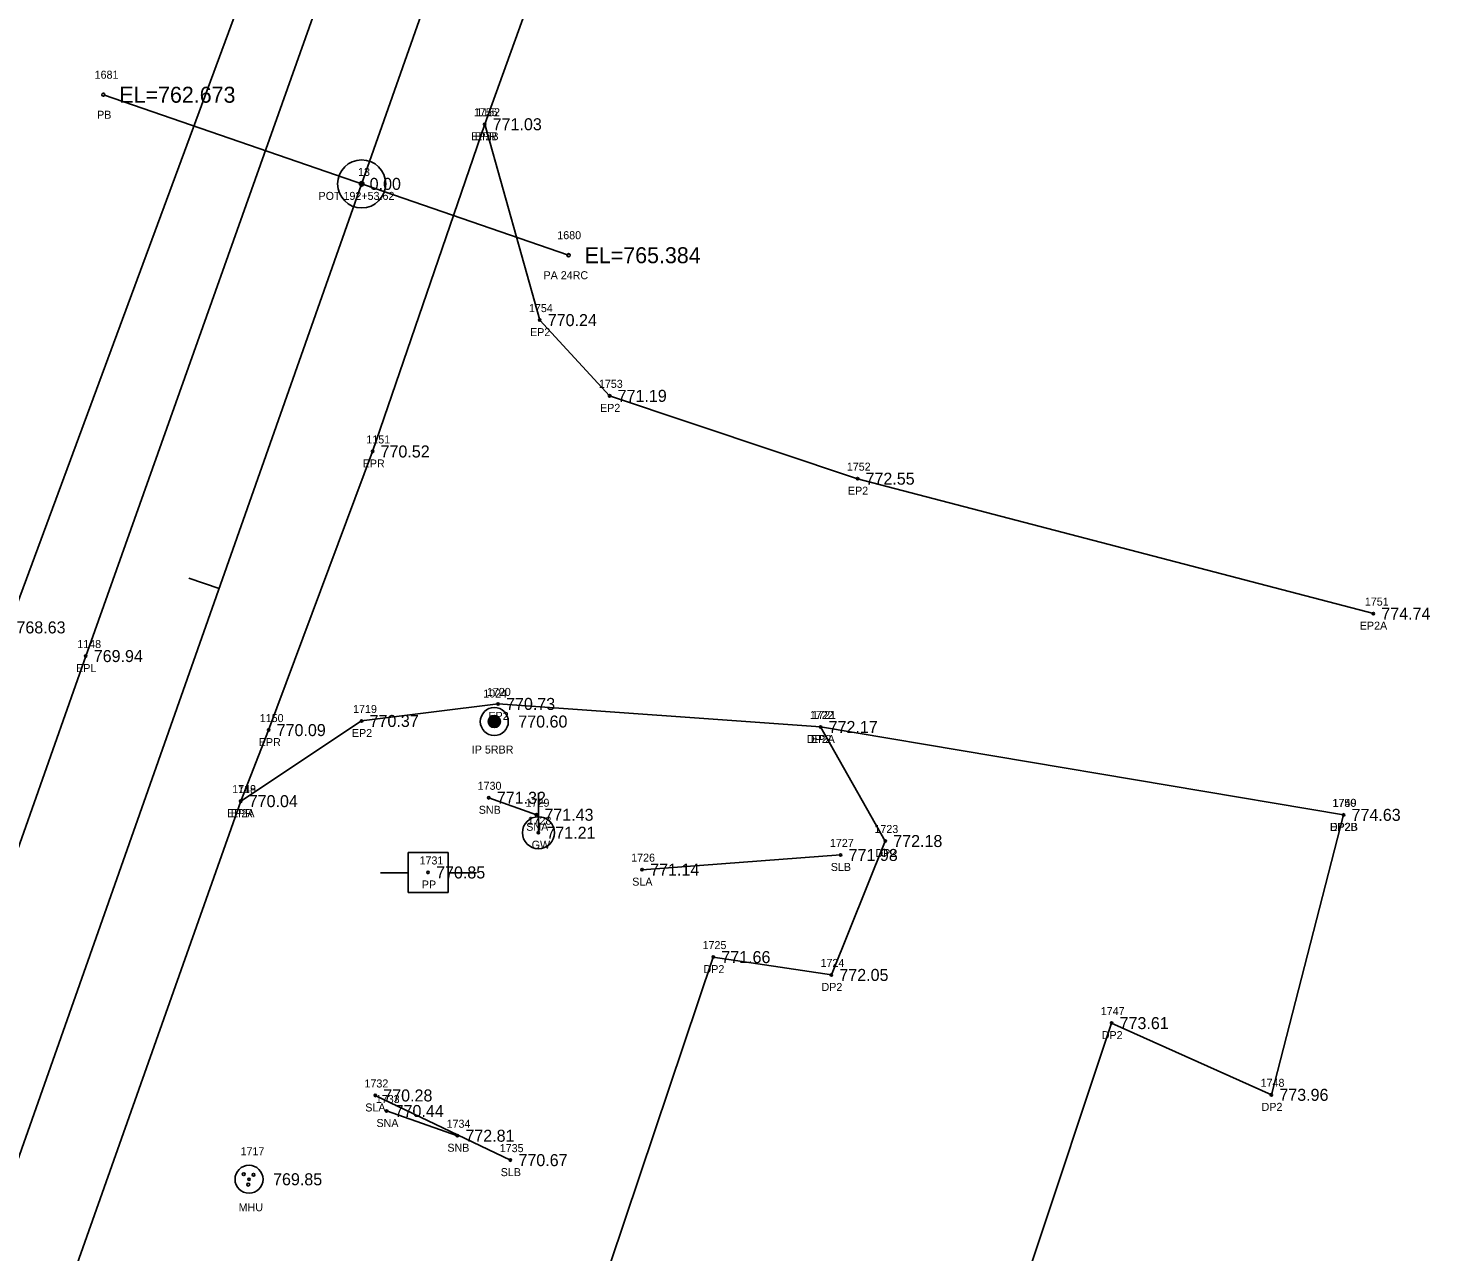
# Model space of a CAD drawing. Extents: x 1736563 to 1738032, y 1150548 to 1154248.
# Drawn here: x 1737815.3 to 1737990.5, y 1153793.3 to 1153946.3 of the extents above; entities that cross this region are included whole.
import ezdxf

# ---------------------------------------------------------------- set-up
doc = ezdxf.new("R2010")
doc.units = 0
for name, color, linetype in [('RD_EX_BldgApp', 7, 'Continuous'), ('RD_EX_BldgApp_txCode', 7, 'Continuous'), ('RD_EX_DR_Inlet', 7, 'Continuous'), ('RD_EX_DR_Pipe', 7, 'Continuous'), ('RD_EX_DR_Pipe_txCode', 7, 'Continuous'), ('RD_EX_Driveway', 7, 'Continuous'), ('RD_EX_Driveway_txCode', 7, 'Continuous'), ('RD_EX_DV_Prop_txCode', 7, 'Continuous'), ('RD_EX_DV_PropPin', 7, 'Continuous'), ('RD_EX_Road', 7, 'Continuous'), ('RD_EX_Road_txCode', 7, 'Continuous'), ('RD_EX_TX_BldgApp_ELEV', 7, 'Continuous'), ('RD_EX_TX_Driveway_ELEV', 7, 'Continuous'), ('RD_EX_TX_DV_Prop_ELEV', 7, 'Continuous'), ('RD_EX_TX_Road_ELEV', 7, 'Continuous'), ('RD_EX_TX_UT_ELEV', 7, 'Continuous'), ('RD_EX_TX_VEG_ELEV', 7, 'Continuous'), ('RD_EX_UT', 7, 'Continuous'), ('RD_EX_UT_txCode', 7, 'Continuous'), ('RD_EX_VEG', 7, 'Continuous'), ('RD_EX_VEG_txCode', 7, 'Continuous'), ('RD_HC_Cl', 7, 'Continuous'), ('RD_HC_Data', 7, 'Continuous'), ('RD_HC_Data_Tic', 7, 'Continuous'), ('RD_HC_Survey_ELEV', 7, 'Continuous'), ('RD_HC_txCode', 7, 'Continuous'), ('RD_SMD_Locator', 7, 'Continuous'), ('RD_TX_Pipe_ElevEX', 7, 'Continuous')]:
    doc.layers.add(name, color=color, linetype=linetype)

msp = doc.modelspace()

# ---------------------------------------------------------------- linework, layer by layer
at = {"layer": 'RD_EX_BldgApp'}
for p, q in [((1737878.86, 1153847.96), (1737872.91, 1153850.08)), ((1737860.15, 1153810.95), (1737868.99, 1153807.86))]:
    msp.add_line(p, q, dxfattribs=at)
at = {"layer": 'RD_EX_DR_Inlet'}
for centre, radius in [((1737842.96, 1153802.42), 1.75), ((1737842.29, 1153803.05), 0.175), ((1737843.52, 1153802.98), 0.175), ((1737842.87, 1153801.75), 0.175)]:
    msp.add_circle(centre, radius, dxfattribs=at)
at = {"layer": 'RD_EX_DR_Pipe'}
msp.add_line((1737882.88, 1153917.87), (1737824.76, 1153937.92), dxfattribs=at)
at = {"layer": 'RD_EX_Driveway'}
msp.add_lwpolyline([(1737914.37, 1153858.93), (1737922.44, 1153844.68), (1737915.71, 1153827.95), (1737900.96, 1153830.18), (1737882.56, 1153775.48), (1737901.6, 1153769.37), (1737890.31, 1153735.49), (1737879.23, 1153704.14), (1737888.54, 1153700.93), (1737902.4, 1153737.89), (1737910.81, 1153737.13), (1737920.2, 1153763.88), (1737930.49, 1153761.11), (1737950.72, 1153821.93), (1737970.68, 1153812.97), (1737979.7, 1153847.95)], dxfattribs=at)
at = {"layer": 'RD_EX_DV_PropPin'}
for p, q in [((1737873.32, 1153858.9), (1737873.32, 1153860.32)), ((1737873.36, 1153858.89), (1737873.36, 1153860.33)), ((1737873.39, 1153858.88), (1737873.39, 1153860.34)), ((1737873.43, 1153858.87), (1737873.43, 1153860.35)), ((1737873.46, 1153858.86), (1737873.46, 1153860.36)), ((1737873.5, 1153858.86), (1737873.5, 1153860.36)), ((1737873.53, 1153858.85), (1737873.53, 1153860.37)), ((1737873.57, 1153858.85), (1737873.57, 1153860.37)), ((1737873.6, 1153858.85), (1737873.6, 1153860.37)), ((1737873.64, 1153858.85), (1737873.64, 1153860.37)), ((1737873.67, 1153858.85), (1737873.67, 1153860.37)), ((1737873.71, 1153858.86), (1737873.71, 1153860.36)), ((1737873.74, 1153858.86), (1737873.74, 1153860.36)), ((1737873.78, 1153858.87), (1737873.78, 1153860.35)), ((1737873.81, 1153858.88), (1737873.81, 1153860.34)), ((1737873.85, 1153858.89), (1737873.85, 1153860.33)), ((1737873.88, 1153858.9), (1737873.88, 1153860.32)), ((1737872.87, 1153859.41), (1737872.87, 1153859.81)), ((1737872.9, 1153859.31), (1737872.9, 1153859.91)), ((1737872.94, 1153859.24), (1737872.94, 1153859.98)), ((1737872.97, 1153859.18), (1737872.97, 1153860.04)), ((1737873.01, 1153859.14), (1737873.01, 1153860.08)), ((1737873.04, 1153859.09), (1737873.04, 1153860.12)), ((1737873.08, 1153859.06), (1737873.08, 1153860.16)), ((1737873.11, 1153859.03), (1737873.11, 1153860.19)), ((1737873.15, 1153859), (1737873.15, 1153860.22)), ((1737873.18, 1153858.98), (1737873.18, 1153860.24)), ((1737873.22, 1153858.95), (1737873.22, 1153860.27)), ((1737873.25, 1153858.93), (1737873.25, 1153860.29)), ((1737873.29, 1153858.92), (1737873.29, 1153860.3)), ((1737873.92, 1153858.92), (1737873.92, 1153860.3)), ((1737873.95, 1153858.93), (1737873.95, 1153860.29)), ((1737873.99, 1153858.95), (1737873.99, 1153860.27)), ((1737874.02, 1153858.98), (1737874.02, 1153860.24)), ((1737874.06, 1153859), (1737874.06, 1153860.22)), ((1737874.09, 1153859.03), (1737874.09, 1153860.19)), ((1737874.13, 1153859.06), (1737874.13, 1153860.16)), ((1737874.16, 1153859.09), (1737874.16, 1153860.12)), ((1737874.2, 1153859.14), (1737874.2, 1153860.08)), ((1737874.23, 1153859.18), (1737874.23, 1153860.04)), ((1737874.27, 1153859.24), (1737874.27, 1153859.98)), ((1737874.3, 1153859.31), (1737874.3, 1153859.91)), ((1737874.34, 1153859.41), (1737874.34, 1153859.81))]:
    msp.add_line(p, q, dxfattribs=at)
for radius in [1.75, 0.761]:
    msp.add_circle((1737873.6, 1153859.61), radius, dxfattribs=at)
at = {"layer": 'RD_EX_Road'}
for points in [[(1737496.36, 1152940.55), (1737529.37, 1153032.75), (1737537.93, 1153057.4), (1737549.32, 1153089.17), (1737563.01, 1153127.73), (1737595.49, 1153219.95), (1737628.15, 1153312.67), (1737660.2, 1153403.8), (1737692.32, 1153495.67), (1737724.61, 1153587.75), (1737756.73, 1153679.29), (1737770.32, 1153718.5), (1737778.01, 1153740.46), (1737788.96, 1153772.48), (1737822.56, 1153867.79), (1737856.1, 1153962.19), (1737875.63, 1154016.18), (1737880.55, 1154030.08), (1737889.82, 1154055.89), (1737923.73, 1154151.97)], [(1737767.23, 1153635.63), (1737779.62, 1153670.7), (1737786.15, 1153689.96), (1737811.86, 1153764.64), (1737841.92, 1153849.66), (1737845.41, 1153858.54), (1737858.39, 1153893.35), (1737872.4, 1153934.23), (1737879.38, 1153953.57), (1737912.95, 1154048.07), (1737946.82, 1154144.4)], [(1737983.42, 1153873.09), (1737918.98, 1153889.95), (1737888.01, 1153900.3), (1737879.28, 1153909.76), (1737872.4, 1153934.23)], [(1737841.92, 1153849.66), (1737857.02, 1153859.68), (1737874.07, 1153861.81), (1737914.37, 1153858.93), (1737979.7, 1153847.95)]]:
    msp.add_lwpolyline(points, dxfattribs=at)
at = {"layer": 'RD_EX_UT'}
for p, q in [((1737879.11, 1153845.72), (1737879.11, 1153850.72)), ((1737867.82, 1153843.26), (1737862.82, 1153843.26)), ((1737862.82, 1153843.26), (1737862.82, 1153838.26)), ((1737867.82, 1153838.26), (1737867.82, 1153843.26)), ((1737859.39, 1153840.7), (1737862.85, 1153840.7)), ((1737867.74, 1153840.7), (1737871.39, 1153840.7)), ((1737862.82, 1153838.26), (1737867.82, 1153838.26))]:
    msp.add_line(p, q, dxfattribs=at)
msp.add_circle((1737879.11, 1153845.72), 2, dxfattribs=at)
at = {"layer": 'RD_EX_VEG'}
for p, q in [((1737892.07, 1153841.1), (1737916.87, 1153842.94)), ((1737858.73, 1153812.89), (1737875.62, 1153804.81))]:
    msp.add_line(p, q, dxfattribs=at)
msp.add_lwpolyline([(1737451.48, 1152925.19), (1737471.83, 1152967.5), (1737483.5, 1153062.03), (1737523.53, 1153143.47), (1737578.4, 1153225.34), (1737613.35, 1153318.74), (1737643.94, 1153407.18), (1737681, 1153500.22), (1737713.81, 1153596.51), (1737742.54, 1153686.46), (1737776.37, 1153777.24), (1737812.9, 1153871.37), (1737847.32, 1153964.45), (1737872.45, 1154065.49)], dxfattribs=at)
at = {"layer": 'RD_HC_Cl'}
msp.add_line((1736879.96, 1151154.46), (1737935.1, 1154148.31), dxfattribs=at)
at = {"layer": 'RD_HC_Data'}
for radius in [3, 0.282]:
    msp.add_circle((1737857.03, 1153926.78), radius, dxfattribs=at)
at = {"layer": 'RD_HC_Data_Tic'}
msp.add_line((1737839.21, 1153876.21), (1737835.43, 1153877.54), dxfattribs=at)
at = {"layer": 'RD_SMD_Locator'}
for centre, radius in [((1737824.76, 1153937.92), 0.2), ((1737872.4, 1153934.23), 0.15), ((1737872.4, 1153934.23), 0.15), ((1737857.03, 1153926.78), 0.15), ((1737882.88, 1153917.87), 0.2), ((1737879.28, 1153909.76), 0.15), ((1737888.01, 1153900.3), 0.15), ((1737858.39, 1153893.35), 0.15), ((1737918.98, 1153889.95), 0.15), ((1737983.42, 1153873.09), 0.15), ((1737822.56, 1153867.79), 0.15), ((1737874.07, 1153861.81), 0.15), ((1737845.41, 1153858.54), 0.15), ((1737857.02, 1153859.68), 0.15), ((1737873.6, 1153859.61), 0.15), ((1737914.37, 1153858.93), 0.15), ((1737914.37, 1153858.93), 0.15), ((1737841.92, 1153849.66), 0.15), ((1737841.92, 1153849.66), 0.15), ((1737872.91, 1153850.08), 0.15), ((1737878.86, 1153847.96), 0.15), ((1737979.7, 1153847.95), 0.15), ((1737979.7, 1153847.95), 0.15), ((1737879.11, 1153845.72), 0.15), ((1737922.44, 1153844.68), 0.15), ((1737916.87, 1153842.94), 0.15), ((1737892.07, 1153841.1), 0.15), ((1737865.33, 1153840.75), 0.15), ((1737900.96, 1153830.18), 0.15), ((1737915.71, 1153827.95), 0.15), ((1737950.72, 1153821.93), 0.15), ((1737858.73, 1153812.89), 0.15), ((1737970.68, 1153812.97), 0.15), ((1737860.15, 1153810.95), 0.15), ((1737868.99, 1153807.86), 0.15), ((1737875.62, 1153804.81), 0.15), ((1737842.96, 1153802.42), 0.15)]:
    msp.add_circle(centre, radius, dxfattribs=at)

# ---------------------------------------------------------------- texts
at = {"layer": 'RD_EX_BldgApp_txCode'}
for s, p in [('1730', (1737871.52, 1153851.08)), ('1729', (1737877.51, 1153848.96)), ('SNB', (1737871.66, 1153848.08)), ('SNA', (1737877.59, 1153845.96)), ('1733', (1737858.8, 1153811.95)), ('SNA', (1737858.88, 1153808.95)), ('1734', (1737867.64, 1153808.86)), ('SNB', (1737867.74, 1153805.86))]:
    msp.add_text(s, height=1, dxfattribs=at).set_placement(p)
at = {"layer": 'RD_EX_DR_Pipe_txCode'}
for s, p in [('1681', (1737823.67, 1153939.92)), ('PB', (1737823.98, 1153934.92)), ('1680', (1737881.47, 1153919.87)), ('PA 24RC', (1737879.75, 1153914.87))]:
    msp.add_text(s, height=1, dxfattribs=at).set_placement(p)
at = {"layer": 'RD_EX_Driveway_txCode'}
for s, p in [('1722', (1737913.02, 1153859.93)), ('DP2A', (1737912.65, 1153856.93)), ('1749', (1737978.35, 1153848.95)), ('1723', (1737921.09, 1153845.68)), ('DP2B', (1737978, 1153845.95)), ('DP2', (1737921.21, 1153842.68)), ('1725', (1737899.62, 1153831.18)), ('DP2', (1737899.74, 1153828.18)), ('1724', (1737914.36, 1153828.95)), ('DP2', (1737914.48, 1153825.95)), ('1747', (1737949.37, 1153822.93)), ('DP2', (1737949.49, 1153819.93)), ('1748', (1737969.34, 1153813.97)), ('DP2', (1737969.46, 1153810.97))]:
    msp.add_text(s, height=1, dxfattribs=at).set_placement(p)
at = {"layer": 'RD_EX_DV_Prop_txCode'}
for s, p in [('1024', (1737872.22, 1153862.61)), ('IP 5RBR', (1737870.79, 1153855.61))]:
    msp.add_text(s, height=1, dxfattribs=at).set_placement(p)
at = {"layer": 'RD_EX_Road_txCode'}
for s, p in [('1755', (1737871.05, 1153935.23)), ('1152', (1737871.34, 1153935.23)), ('EP2B', (1737870.72, 1153932.23)), ('EPR', (1737871.17, 1153932.23)), ('1754', (1737877.93, 1153910.76)), ('EP2', (1737878.07, 1153907.76)), ('1753', (1737886.67, 1153901.3)), ('EP2', (1737886.81, 1153898.3)), ('1151', (1737857.61, 1153894.35)), ('EPR', (1737857.16, 1153891.35)), ('1752', (1737917.64, 1153890.95)), ('EP2', (1737917.78, 1153887.95)), ('1751', (1737982.36, 1153874.09)), ('EP2A', (1737981.73, 1153871.09)), ('1148', (1737821.5, 1153868.79)), ('EPL', (1737821.36, 1153865.79)), ('1720', (1737872.68, 1153862.81)), ('1150', (1737844.3, 1153859.54)), ('1719', (1737855.96, 1153860.68)), ('EP2', (1737872.87, 1153859.81)), ('1721', (1737913.3, 1153859.93)), ('EP2', (1737855.81, 1153857.68)), ('EPR', (1737844.18, 1153856.54)), ('EP2', (1737913.16, 1153856.93)), ('1149', (1737840.85, 1153850.66)), ('1718', (1737840.85, 1153850.66)), ('1750', (1737978.31, 1153848.95)), ('EP2A', (1737840.22, 1153847.66)), ('EPR', (1737840.69, 1153847.66)), ('EP2B', (1737978.02, 1153845.95))]:
    msp.add_text(s, height=1, dxfattribs=at).set_placement(p)
at = {"layer": 'RD_EX_TX_BldgApp_ELEV'}
for s, p in [('771.32', (1737873.91, 1153849.33)), ('771.43', (1737879.86, 1153847.21)), ('770.44', (1737861.15, 1153810.2)), ('772.81', (1737869.99, 1153807.11))]:
    msp.add_text(s, height=1.5, dxfattribs=at).set_placement(p)
at = {"layer": 'RD_EX_TX_Driveway_ELEV'}
for s, p in [('772.17', (1737915.37, 1153858.18)), ('774.63', (1737980.7, 1153847.2)), ('772.18', (1737923.44, 1153843.93)), ('771.66', (1737901.96, 1153829.43)), ('772.05', (1737916.71, 1153827.2)), ('773.61', (1737951.72, 1153821.18)), ('773.96', (1737971.68, 1153812.22))]:
    msp.add_text(s, height=1.5, dxfattribs=at).set_placement(p)
at = {"layer": 'RD_EX_TX_DV_Prop_ELEV'}
msp.add_text('770.60', height=1.5, dxfattribs=at).set_placement((1737876.6, 1153858.86))
at = {"layer": 'RD_EX_TX_Road_ELEV'}
for s, p in [('771.03', (1737873.4, 1153933.48)), ('771.03', (1737873.4, 1153933.48)), ('770.24', (1737880.28, 1153909.01)), ('771.19', (1737889.01, 1153899.55)), ('770.52', (1737859.39, 1153892.6)), ('772.55', (1737919.98, 1153889.2)), ('774.74', (1737984.42, 1153872.34)), ('769.94', (1737823.56, 1153867.04)), ('770.73', (1737875.07, 1153861.06)), ('770.37', (1737858.02, 1153858.93)), ('770.09', (1737846.41, 1153857.79)), ('772.17', (1737915.37, 1153858.18)), ('770.04', (1737842.92, 1153848.91)), ('770.04', (1737842.92, 1153848.91)), ('774.63', (1737980.7, 1153847.2))]:
    msp.add_text(s, height=1.5, dxfattribs=at).set_placement(p)
at = {"layer": 'RD_EX_TX_UT_ELEV'}
for s, p in [('771.21', (1737880.11, 1153844.97)), ('769.85', (1737845.96, 1153801.67))]:
    msp.add_text(s, height=1.5, dxfattribs=at).set_placement(p)
at = {"layer": 'RD_EX_TX_VEG_ELEV'}
for s, p in [('768.63', (1737813.9, 1153870.62)), ('771.98', (1737917.87, 1153842.19)), ('771.14', (1737893.07, 1153840.35)), ('770.28', (1737859.73, 1153812.14)), ('770.67', (1737876.62, 1153804.06))]:
    msp.add_text(s, height=1.5, dxfattribs=at).set_placement(p)
at = {"layer": 'RD_EX_UT_txCode'}
for s, p in [('1728', (1737877.76, 1153846.72)), ('GW', (1737878.27, 1153843.72)), ('1731', (1737864.26, 1153841.75)), ('PP', (1737864.55, 1153838.75)), ('1717', (1737841.9, 1153805.42)), ('MHU', (1737841.66, 1153798.42))]:
    msp.add_text(s, height=1, dxfattribs=at).set_placement(p)
at = {"layer": 'RD_EX_VEG_txCode'}
for s, p in [('1727', (1737915.53, 1153843.94)), ('1726', (1737890.7, 1153842.1)), ('SLB', (1737915.64, 1153840.94)), ('SLA', (1737890.83, 1153839.1)), ('1732', (1737857.38, 1153813.89)), ('SLA', (1737857.48, 1153810.89)), ('1735', (1737874.28, 1153805.81)), ('SLB', (1737874.4, 1153802.81))]:
    msp.add_text(s, height=1, dxfattribs=at).set_placement(p)
at = {"layer": 'RD_HC_Survey_ELEV'}
for s, p in [('0.00', (1737858.03, 1153926.03)), ('770.85', (1737866.33, 1153840))]:
    msp.add_text(s, height=1.5, dxfattribs=at).set_placement(p)
at = {"layer": 'RD_HC_txCode'}
for s, p in [('13', (1737856.58, 1153927.78)), ('POT 192+53.62', (1737851.64, 1153924.78))]:
    msp.add_text(s, height=1, dxfattribs=at).set_placement(p)
at = {"layer": 'RD_TX_Pipe_ElevEX'}
for s, p in [('EL=762.673', (1737826.76, 1153936.92)), ('EL=765.384', (1737884.88, 1153916.87))]:
    msp.add_text(s, height=2, dxfattribs=at).set_placement(p)

doc.saveas('drawing.dxf')
